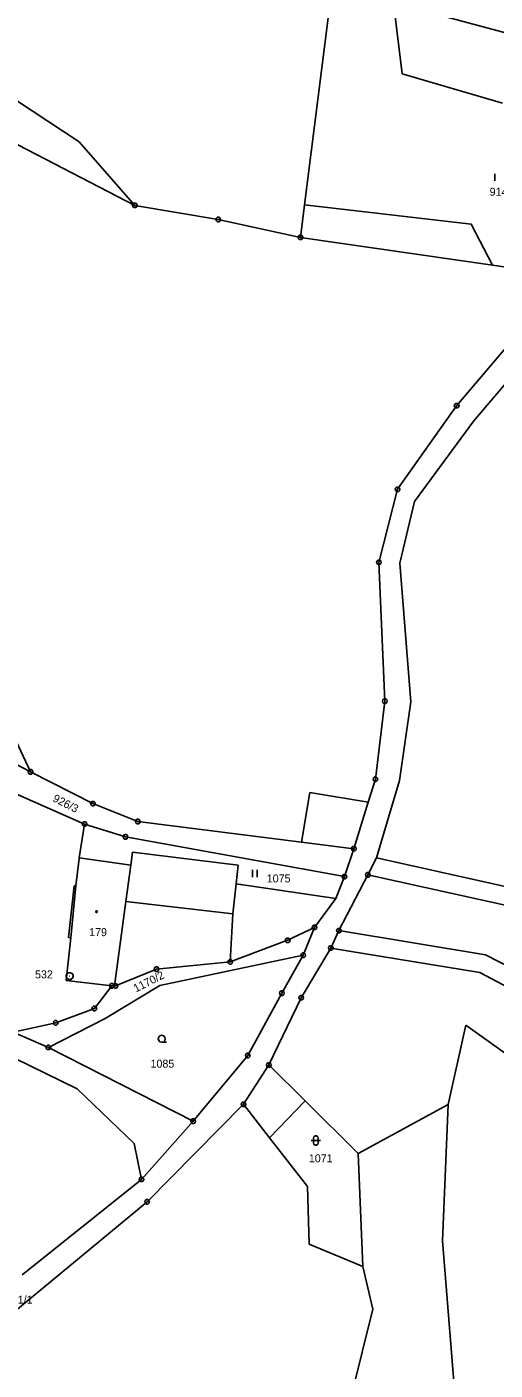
# Model space of a CAD drawing. Extents: x -694465 to -690527, y -983694 to -978978.
# Drawn here: x -691544 to -691444.6, y -981397.2 to -981111.8 of the extents above; entities that cross this region are included whole.
import ezdxf

# ---------------------------------------------------------------- set-up
doc = ezdxf.new("R2010")
doc.units = 0
for name, color, linetype in [('Vrstva 1', 7, 'Continuous'), ('Vrstva 17', 7, 'Continuous'), ('Vrstva 18', 7, 'Continuous'), ('Vrstva 19', 7, 'Continuous'), ('Vrstva 24', 7, 'Continuous'), ('Vrstva 25', 7, 'Continuous'), ('Vrstva 60', 7, 'Continuous')]:
    doc.layers.add(name, color=color, linetype=linetype)

msp = doc.modelspace()

# ---------------------------------------------------------------- linework, layer by layer
at = {"layer": 'Vrstva 1'}
for p, q in [((-691485.715, -981285.047), (-691483.905, -981274.509)), ((-691483.905, -981274.509), (-691471.51, -981276.543))]:
    msp.add_line(p, q, dxfattribs=at)
for points in [[(-691485.039, -981149.655), (-691478.61, -981098.68)], [(-691466.12, -981106.76), (-691464.3, -981121.8)], [(-691464.3, -981121.8), (-691443.02, -981128.06)], [(-691532.9, -981136.26), (-691549.52, -981125.29)], [(-691563.08, -981128.05), (-691521.1, -981149.76)], [(-691521.1, -981149.76), (-691532.9, -981136.26)], [(-691521.1, -981149.76), (-691503.37, -981152.76)], [(-691485.91, -981156.56), (-691485.039, -981149.655)], [(-691485.039, -981149.655), (-691449.639, -981153.738), (-691445.151, -981162.47)], [(-691503.37, -981152.76), (-691485.91, -981156.56)], [(-691445.151, -981162.47), (-691485.91, -981156.56)], [(-691430.12, -981164.65), (-691445.151, -981162.47)], [(-691438.64, -981175.76), (-691452.73, -981192.33)], [(-691449.1, -981195.51), (-691434.84, -981178.86)], [(-691452.73, -981192.33), (-691465.27, -981210.09)], [(-691461.69, -981212.7), (-691449.1, -981195.51)], [(-691465.27, -981210.09), (-691469.24, -981225.61)], [(-691464.77, -981225.79), (-691461.69, -981212.7)], [(-691469.24, -981225.61), (-691467.99, -981255.1)], [(-691462.47, -981255.24), (-691464.77, -981225.79)], [(-691558.55, -981237.51), (-691543.26, -981270.11)], [(-691467.99, -981255.1), (-691470, -981271.67)], [(-691464.89, -981271.95), (-691462.47, -981255.24)], [(-691543.26, -981270.11), (-691561.03, -981260.84)], [(-691529.99, -981276.86), (-691543.26, -981270.11)], [(-691470, -981271.67), (-691471.51, -981276.543)], [(-691469.77, -981288.4), (-691464.89, -981271.95)], [(-691550.26, -981273.12), (-691531.76, -981281.2)], [(-691520.46, -981280.67), (-691529.99, -981276.86)], [(-691471.51, -981276.543), (-691474.58, -981286.45)], [(-691531.76, -981281.2), (-691532.912, -981288.395)], [(-691531.76, -981281.2), (-691523.06, -981283.93)], [(-691485.715, -981285.047), (-691520.46, -981280.67)], [(-691523.06, -981283.93), (-691476.57, -981292.38)], [(-691521.944, -981289.946), (-691521.567, -981287.173)], [(-691499.124, -981289.927), (-691521.567, -981287.173)], [(-691474.58, -981286.45), (-691485.715, -981285.047)], [(-691474.58, -981286.45), (-691476.57, -981292.38)], [(-691532.93, -981288.51), (-691533.59, -981294.35)], [(-691532.912, -981288.395), (-691532.93, -981288.51)], [(-691521.944, -981289.946), (-691532.912, -981288.395)], [(-691522.998, -981297.698), (-691521.944, -981289.946)], [(-691499.57, -981293.89), (-691499.124, -981289.927)], [(-691469.77, -981288.4), (-691471.59, -981292.01)], [(-691332.82, -981318.91), (-691469.77, -981288.4)], [(-691476.57, -981292.38), (-691478.43, -981297.02)], [(-691477.74, -981303.85), (-691471.59, -981292.01)], [(-691471.59, -981292.01), (-691400.41, -981307.73)], [(-691533.95, -981294.31), (-691535.19, -981305.3)], [(-691533.59, -981294.35), (-691534.68, -981305.36)], [(-691533.59, -981294.35), (-691533.95, -981294.31)], [(-691499.57, -981293.89), (-691500.29, -981300.26)], [(-691478.43, -981297.02), (-691499.57, -981293.89)], [(-691525.43, -981315.594), (-691522.998, -981297.698)], [(-691500.29, -981300.26), (-691522.998, -981297.698)], [(-691478.43, -981297.02), (-691482.92, -981303.17)], [(-691500.29, -981300.26), (-691500.81, -981310.48)], [(-691482.92, -981303.17), (-691488.63, -981305.91)], [(-691485.31, -981309.08), (-691482.92, -981303.17)], [(-691477.74, -981303.85), (-691479.48, -981307.55)], [(-691446.64, -981308.98), (-691477.74, -981303.85)], [(-691534.68, -981305.36), (-691535.7, -981314.42)], [(-691535.19, -981305.3), (-691534.68, -981305.36)], [(-691488.63, -981305.91), (-691500.81, -981310.48)], [(-691515.81, -981315.5), (-691485.31, -981309.08)], [(-691485.31, -981309.08), (-691489.86, -981317.14)], [(-691485.74, -981318.1), (-691479.48, -981307.55)], [(-691479.48, -981307.55), (-691447.83, -981312.77)], [(-691424.36, -981320.4), (-691446.64, -981308.98)], [(-691516.48, -981312.03), (-691525.18, -981315.6)], [(-691500.81, -981310.48), (-691516.48, -981312.03)], [(-691447.83, -981312.77), (-691425.25, -981324.69)], [(-691535.7, -981314.42), (-691525.98, -981315.58)], [(-691525.98, -981315.58), (-691529.69, -981320.4)], [(-691527.37, -981322.49), (-691515.81, -981315.5)], [(-691525.43, -981315.594), (-691525.98, -981315.58)], [(-691525.18, -981315.6), (-691525.43, -981315.594)], [(-691489.86, -981317.14), (-691497.11, -981330.38)], [(-691492.62, -981332.4), (-691485.74, -981318.1)], [(-691566.58, -981321.214), (-691533.32, -981337.46)], [(-691529.69, -981320.4), (-691537.9, -981323.44)], [(-691537.9, -981323.44), (-691546.94, -981325.41)], [(-691539.46, -981328.66), (-691527.37, -981322.49)], [(-691450.75, -981323.94), (-691454.53, -981340.76)], [(-691376.08, -981377.32), (-691450.75, -981323.94)], [(-691546.94, -981325.41), (-691539.46, -981328.66)], [(-691508.7, -981344.34), (-691539.46, -981328.66)], [(-691497.11, -981330.38), (-691508.7, -981344.34)], [(-691492.62, -981332.4), (-691497.99, -981340.75)], [(-691484.924, -981340.039), (-691492.62, -981332.4)], [(-691533.32, -981337.46), (-691521.21, -981349.05)], [(-691518.49, -981361.48), (-691497.99, -981340.75)], [(-691497.99, -981340.75), (-691492.487, -981347.848)], [(-691484.924, -981340.039), (-691492.487, -981347.848)], [(-691473.67, -981351.21), (-691484.924, -981340.039)], [(-691454.53, -981340.76), (-691473.67, -981351.21)], [(-691454.53, -981340.76), (-691455.74, -981369.75)], [(-691519.66, -981356.71), (-691508.7, -981344.34)], [(-691521.21, -981349.05), (-691519.66, -981356.71)], [(-691492.487, -981347.848), (-691484.43, -981358.24)], [(-691472.68, -981375.18), (-691473.67, -981351.21)], [(-691519.66, -981356.71), (-691545.016, -981376.977)], [(-691484.43, -981358.24), (-691484.03, -981370.49)], [(-691557.12, -981393.42), (-691518.49, -981361.48)], [(-691455.74, -981369.75), (-691450.4, -981435.73)], [(-691484.03, -981370.49), (-691472.68, -981375.18)], [(-691472.68, -981375.18), (-691470.56, -981384.3)], [(-691470.56, -981384.3), (-691475.02, -981402.29)]]:
    msp.add_lwpolyline(points, dxfattribs=at)
at = {"layer": 'Vrstva 24'}
for points in [[(-691520.946, -981149.284), (-691520.696, -981149.466), (-691520.6, -981149.76), (-691520.696, -981150.054), (-691520.946, -981150.236), (-691521.254, -981150.236), (-691521.504, -981150.054), (-691521.6, -981149.76), (-691521.504, -981149.466), (-691521.254, -981149.284)], [(-691503.216, -981152.284), (-691502.966, -981152.466), (-691502.87, -981152.76), (-691502.966, -981153.054), (-691503.216, -981153.236), (-691503.524, -981153.236), (-691503.774, -981153.054), (-691503.87, -981152.76), (-691503.774, -981152.466), (-691503.524, -981152.284)], [(-691485.756, -981156.084), (-691485.506, -981156.266), (-691485.41, -981156.56), (-691485.506, -981156.854), (-691485.756, -981157.036), (-691486.064, -981157.036), (-691486.314, -981156.854), (-691486.41, -981156.56), (-691486.314, -981156.266), (-691486.064, -981156.084)], [(-691452.576, -981191.854), (-691452.326, -981192.036), (-691452.23, -981192.33), (-691452.326, -981192.624), (-691452.576, -981192.806), (-691452.884, -981192.806), (-691453.134, -981192.624), (-691453.23, -981192.33), (-691453.134, -981192.036), (-691452.884, -981191.854)], [(-691465.116, -981209.614), (-691464.866, -981209.796), (-691464.77, -981210.09), (-691464.866, -981210.384), (-691465.116, -981210.566), (-691465.424, -981210.566), (-691465.674, -981210.384), (-691465.77, -981210.09), (-691465.674, -981209.796), (-691465.424, -981209.614)], [(-691469.086, -981225.134), (-691468.836, -981225.316), (-691468.74, -981225.61), (-691468.836, -981225.904), (-691469.086, -981226.086), (-691469.394, -981226.086), (-691469.644, -981225.904), (-691469.74, -981225.61), (-691469.644, -981225.316), (-691469.394, -981225.134)], [(-691467.836, -981254.624), (-691467.586, -981254.806), (-691467.49, -981255.1), (-691467.586, -981255.394), (-691467.836, -981255.576), (-691468.144, -981255.576), (-691468.394, -981255.394), (-691468.49, -981255.1), (-691468.394, -981254.806), (-691468.144, -981254.624)], [(-691543.106, -981269.634), (-691542.856, -981269.816), (-691542.76, -981270.11), (-691542.856, -981270.404), (-691543.106, -981270.586), (-691543.414, -981270.586), (-691543.664, -981270.404), (-691543.76, -981270.11), (-691543.664, -981269.816), (-691543.414, -981269.634)], [(-691469.846, -981271.194), (-691469.596, -981271.376), (-691469.5, -981271.67), (-691469.596, -981271.964), (-691469.846, -981272.146), (-691470.154, -981272.146), (-691470.404, -981271.964), (-691470.5, -981271.67), (-691470.404, -981271.376), (-691470.154, -981271.194)], [(-691529.836, -981276.384), (-691529.586, -981276.566), (-691529.49, -981276.86), (-691529.586, -981277.154), (-691529.836, -981277.336), (-691530.144, -981277.336), (-691530.394, -981277.154), (-691530.49, -981276.86), (-691530.394, -981276.566), (-691530.144, -981276.384)], [(-691531.606, -981280.724), (-691531.356, -981280.906), (-691531.26, -981281.2), (-691531.356, -981281.494), (-691531.606, -981281.676), (-691531.914, -981281.676), (-691532.164, -981281.494), (-691532.26, -981281.2), (-691532.164, -981280.906), (-691531.914, -981280.724)], [(-691520.306, -981280.194), (-691520.056, -981280.376), (-691519.96, -981280.67), (-691520.056, -981280.964), (-691520.306, -981281.146), (-691520.614, -981281.146), (-691520.864, -981280.964), (-691520.96, -981280.67), (-691520.864, -981280.376), (-691520.614, -981280.194)], [(-691522.906, -981283.454), (-691522.656, -981283.636), (-691522.56, -981283.93), (-691522.656, -981284.224), (-691522.906, -981284.406), (-691523.214, -981284.406), (-691523.464, -981284.224), (-691523.56, -981283.93), (-691523.464, -981283.636), (-691523.214, -981283.454)], [(-691474.426, -981285.974), (-691474.176, -981286.156), (-691474.08, -981286.45), (-691474.176, -981286.744), (-691474.426, -981286.926), (-691474.734, -981286.926), (-691474.984, -981286.744), (-691475.08, -981286.45), (-691474.984, -981286.156), (-691474.734, -981285.974)], [(-691476.416, -981291.904), (-691476.166, -981292.086), (-691476.07, -981292.38), (-691476.166, -981292.674), (-691476.416, -981292.856), (-691476.724, -981292.856), (-691476.974, -981292.674), (-691477.07, -981292.38), (-691476.974, -981292.086), (-691476.724, -981291.904)], [(-691471.436, -981291.534), (-691471.186, -981291.716), (-691471.09, -981292.01), (-691471.186, -981292.304), (-691471.436, -981292.486), (-691471.744, -981292.486), (-691471.994, -981292.304), (-691472.09, -981292.01), (-691471.994, -981291.716), (-691471.744, -981291.534)], [(-691482.766, -981302.694), (-691482.516, -981302.876), (-691482.42, -981303.17), (-691482.516, -981303.464), (-691482.766, -981303.646), (-691483.074, -981303.646), (-691483.324, -981303.464), (-691483.42, -981303.17), (-691483.324, -981302.876), (-691483.074, -981302.694)], [(-691477.586, -981303.374), (-691477.336, -981303.556), (-691477.24, -981303.85), (-691477.336, -981304.144), (-691477.586, -981304.326), (-691477.894, -981304.326), (-691478.144, -981304.144), (-691478.24, -981303.85), (-691478.144, -981303.556), (-691477.894, -981303.374)], [(-691488.476, -981305.434), (-691488.226, -981305.616), (-691488.13, -981305.91), (-691488.226, -981306.204), (-691488.476, -981306.386), (-691488.784, -981306.386), (-691489.034, -981306.204), (-691489.13, -981305.91), (-691489.034, -981305.616), (-691488.784, -981305.434)], [(-691479.326, -981307.074), (-691479.076, -981307.256), (-691478.98, -981307.55), (-691479.076, -981307.844), (-691479.326, -981308.026), (-691479.634, -981308.026), (-691479.884, -981307.844), (-691479.98, -981307.55), (-691479.884, -981307.256), (-691479.634, -981307.074)], [(-691500.656, -981310.004), (-691500.406, -981310.186), (-691500.31, -981310.48), (-691500.406, -981310.774), (-691500.656, -981310.956), (-691500.964, -981310.956), (-691501.214, -981310.774), (-691501.31, -981310.48), (-691501.214, -981310.186), (-691500.964, -981310.004)], [(-691485.156, -981308.604), (-691484.906, -981308.786), (-691484.81, -981309.08), (-691484.906, -981309.374), (-691485.156, -981309.556), (-691485.464, -981309.556), (-691485.714, -981309.374), (-691485.81, -981309.08), (-691485.714, -981308.786), (-691485.464, -981308.604)], [(-691534.746, -981312.786), (-691534.41, -981312.98), (-691534.216, -981313.316), (-691534.216, -981313.704), (-691534.41, -981314.04), (-691534.746, -981314.234), (-691535.134, -981314.234), (-691535.47, -981314.04), (-691535.664, -981313.704), (-691535.664, -981313.316), (-691535.47, -981312.98), (-691535.134, -981312.786)], [(-691516.326, -981311.554), (-691516.076, -981311.736), (-691515.98, -981312.03), (-691516.076, -981312.324), (-691516.326, -981312.506), (-691516.634, -981312.506), (-691516.884, -981312.324), (-691516.98, -981312.03), (-691516.884, -981311.736), (-691516.634, -981311.554)], [(-691525.826, -981315.104), (-691525.576, -981315.286), (-691525.48, -981315.58), (-691525.576, -981315.874), (-691525.826, -981316.056), (-691526.134, -981316.056), (-691526.384, -981315.874), (-691526.48, -981315.58), (-691526.384, -981315.286), (-691526.134, -981315.104)], [(-691525.026, -981315.124), (-691524.776, -981315.306), (-691524.68, -981315.6), (-691524.776, -981315.894), (-691525.026, -981316.076), (-691525.334, -981316.076), (-691525.584, -981315.894), (-691525.68, -981315.6), (-691525.584, -981315.306), (-691525.334, -981315.124)], [(-691489.706, -981316.664), (-691489.456, -981316.846), (-691489.36, -981317.14), (-691489.456, -981317.434), (-691489.706, -981317.616), (-691490.014, -981317.616), (-691490.264, -981317.434), (-691490.36, -981317.14), (-691490.264, -981316.846), (-691490.014, -981316.664)], [(-691485.586, -981317.624), (-691485.336, -981317.806), (-691485.24, -981318.1), (-691485.336, -981318.394), (-691485.586, -981318.576), (-691485.894, -981318.576), (-691486.144, -981318.394), (-691486.24, -981318.1), (-691486.144, -981317.806), (-691485.894, -981317.624)], [(-691529.536, -981319.924), (-691529.286, -981320.106), (-691529.19, -981320.4), (-691529.286, -981320.694), (-691529.536, -981320.876), (-691529.844, -981320.876), (-691530.094, -981320.694), (-691530.19, -981320.4), (-691530.094, -981320.106), (-691529.844, -981319.924)], [(-691537.746, -981322.964), (-691537.496, -981323.146), (-691537.4, -981323.44), (-691537.496, -981323.734), (-691537.746, -981323.916), (-691538.054, -981323.916), (-691538.304, -981323.734), (-691538.4, -981323.44), (-691538.304, -981323.146), (-691538.054, -981322.964)], [(-691539.306, -981328.184), (-691539.056, -981328.366), (-691538.96, -981328.66), (-691539.056, -981328.954), (-691539.306, -981329.136), (-691539.614, -981329.136), (-691539.864, -981328.954), (-691539.96, -981328.66), (-691539.864, -981328.366), (-691539.614, -981328.184)], [(-691496.956, -981329.904), (-691496.706, -981330.086), (-691496.61, -981330.38), (-691496.706, -981330.674), (-691496.956, -981330.856), (-691497.264, -981330.856), (-691497.514, -981330.674), (-691497.61, -981330.38), (-691497.514, -981330.086), (-691497.264, -981329.904)], [(-691492.466, -981331.924), (-691492.216, -981332.106), (-691492.12, -981332.4), (-691492.216, -981332.694), (-691492.466, -981332.876), (-691492.774, -981332.876), (-691493.024, -981332.694), (-691493.12, -981332.4), (-691493.024, -981332.106), (-691492.774, -981331.924)], [(-691497.836, -981340.274), (-691497.586, -981340.456), (-691497.49, -981340.75), (-691497.586, -981341.044), (-691497.836, -981341.226), (-691498.144, -981341.226), (-691498.394, -981341.044), (-691498.49, -981340.75), (-691498.394, -981340.456), (-691498.144, -981340.274)], [(-691508.546, -981343.864), (-691508.296, -981344.046), (-691508.2, -981344.34), (-691508.296, -981344.634), (-691508.546, -981344.816), (-691508.854, -981344.816), (-691509.104, -981344.634), (-691509.2, -981344.34), (-691509.104, -981344.046), (-691508.854, -981343.864)], [(-691519.506, -981356.234), (-691519.256, -981356.416), (-691519.16, -981356.71), (-691519.256, -981357.004), (-691519.506, -981357.186), (-691519.814, -981357.186), (-691520.064, -981357.004), (-691520.16, -981356.71), (-691520.064, -981356.416), (-691519.814, -981356.234)], [(-691518.336, -981361.004), (-691518.086, -981361.186), (-691517.99, -981361.48), (-691518.086, -981361.774), (-691518.336, -981361.956), (-691518.644, -981361.956), (-691518.894, -981361.774), (-691518.99, -981361.48), (-691518.894, -981361.186), (-691518.644, -981361.004)]]:
    msp.add_lwpolyline(points, close=True, dxfattribs=at)
for points in [[(-691521.219, -981149.76), (-691520.98, -981149.76)], [(-691503.489, -981152.76), (-691503.25, -981152.76)], [(-691486.029, -981156.56), (-691485.79, -981156.56)], [(-691452.849, -981192.33), (-691452.61, -981192.33)], [(-691465.389, -981210.09), (-691465.15, -981210.09)], [(-691469.359, -981225.61), (-691469.12, -981225.61)], [(-691468.109, -981255.1), (-691467.87, -981255.1)], [(-691543.379, -981270.11), (-691543.14, -981270.11)], [(-691470.119, -981271.67), (-691469.88, -981271.67)], [(-691530.109, -981276.86), (-691529.87, -981276.86)], [(-691531.879, -981281.2), (-691531.64, -981281.2)], [(-691520.579, -981280.67), (-691520.34, -981280.67)], [(-691523.179, -981283.93), (-691522.94, -981283.93)], [(-691474.699, -981286.45), (-691474.46, -981286.45)], [(-691476.689, -981292.38), (-691476.45, -981292.38)], [(-691471.709, -981292.01), (-691471.47, -981292.01)], [(-691483.039, -981303.17), (-691482.8, -981303.17)], [(-691477.859, -981303.85), (-691477.62, -981303.85)], [(-691488.749, -981305.91), (-691488.51, -981305.91)], [(-691485.429, -981309.08), (-691485.19, -981309.08)], [(-691479.599, -981307.55), (-691479.36, -981307.55)], [(-691516.599, -981312.03), (-691516.36, -981312.03)], [(-691500.929, -981310.48), (-691500.69, -981310.48)], [(-691534.99, -981313.51), (-691534.89, -981313.51)], [(-691526.099, -981315.58), (-691525.86, -981315.58)], [(-691525.299, -981315.6), (-691525.06, -981315.6)], [(-691489.979, -981317.14), (-691489.74, -981317.14)], [(-691485.859, -981318.1), (-691485.62, -981318.1)], [(-691529.809, -981320.4), (-691529.57, -981320.4)], [(-691538.019, -981323.44), (-691537.78, -981323.44)], [(-691539.579, -981328.66), (-691539.34, -981328.66)], [(-691497.229, -981330.38), (-691496.99, -981330.38)], [(-691492.739, -981332.4), (-691492.5, -981332.4)], [(-691498.109, -981340.75), (-691497.87, -981340.75)], [(-691508.819, -981344.34), (-691508.58, -981344.34)], [(-691519.779, -981356.71), (-691519.54, -981356.71)], [(-691518.609, -981361.48), (-691518.37, -981361.48)]]:
    msp.add_lwpolyline(points, dxfattribs=at)
at = {"layer": 'Vrstva 25'}
for points in [[(-691444.62, -981143.07), (-691444.62, -981144.57)], [(-691496.1, -981290.96), (-691496.1, -981292.46)], [(-691495.1, -981292.46), (-691495.1, -981290.96)], [(-691515.37, -981327.57), (-691515.745, -981327.469), (-691516.019, -981327.195), (-691516.12, -981326.82), (-691516.019, -981326.445), (-691515.745, -981326.171), (-691515.37, -981326.07), (-691514.995, -981326.171), (-691514.721, -981326.445), (-691514.62, -981326.82), (-691514.721, -981327.195), (-691514.995, -981327.469), (-691515.37, -981327.57), (-691514.37, -981327.571)], [(-691483.65, -981348.46), (-691481.65, -981348.46)]]:
    msp.add_lwpolyline(points, dxfattribs=at)
for points in [[(-691529.143, -981299.678), (-691529.055, -981299.83), (-691529.143, -981299.982), (-691529.317, -981299.982), (-691529.405, -981299.83), (-691529.317, -981299.678)], [(-691483.15, -981347.96), (-691483.055, -981347.666), (-691482.805, -981347.484), (-691482.495, -981347.484), (-691482.245, -981347.666), (-691482.15, -981347.96), (-691482.15, -981348.96), (-691482.245, -981349.254), (-691482.495, -981349.436), (-691482.805, -981349.436), (-691483.055, -981349.254), (-691483.15, -981348.96)]]:
    msp.add_lwpolyline(points, close=True, dxfattribs=at)
at = {"layer": 'Vrstva 60'}
msp.add_line((-691466.12, -981106.76), (-691428.41, -981116.87), dxfattribs=at)

# ---------------------------------------------------------------- texts
at = {"layer": 'Vrstva 17'}
msp.add_text('532', height=1.7, dxfattribs=at).set_placement((-691542.294, -981314))
at = {"layer": 'Vrstva 18'}
for s, p in [('914', (-691445.726, -981147.72)), ('1075', (-691493.069, -981293.61)), ('1085', (-691517.766, -981332.97)), ('1071', (-691484.134, -981353.08)), ('1161/1', (-691549.747, -981383.11))]:
    msp.add_text(s, height=1.7, dxfattribs=at).set_placement(p)
for s, rotation, p in [('926/3', 333.00307, (-691538.688, -981276.298)), ('1170/2', 26.98631, (-691520.847, -981317.012))]:
    msp.add_text(s, height=1.7, rotation=rotation, dxfattribs=at).set_placement(p)
at = {"layer": 'Vrstva 19'}
msp.add_text('179', height=1.7, dxfattribs=at).set_placement((-691530.796, -981305.03))

doc.saveas('drawing.dxf')
